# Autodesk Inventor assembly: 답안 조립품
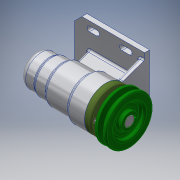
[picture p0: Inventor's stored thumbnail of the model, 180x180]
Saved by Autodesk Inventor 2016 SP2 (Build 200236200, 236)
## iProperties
Created: 2017-09
Part Number: 답안 조립품
Document SubType Name: Assembly
Designer: Administrator
Author: Administrator
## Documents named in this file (12)
- D:\470907V1013\답안 조립품.iam
- D:\470907V1013\본체.ipt
- D:\470907V1013\베어링 51202.ipt
- D:\470907V1013\볼트 M4 x 12.ipt
- D:\470907V1013\어댑터슬리브.ipt
- D:\470907V1013\오일 실 20x35x7.ipt
- D:\470907V1013\축.ipt
- D:\470907V1013\커버.ipt
- D:\470907V1013\키 5 x 5 x 16.ipt
- D:\470907V1013\V벨트풀리.ipt
- D:\470907V1013\멈춤나사 M3x8.ipt
- D:\470907V1013\베어링 6004.ipt
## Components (1 placed, 1 different names)
1. V벨트풀리:1
